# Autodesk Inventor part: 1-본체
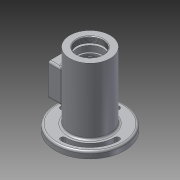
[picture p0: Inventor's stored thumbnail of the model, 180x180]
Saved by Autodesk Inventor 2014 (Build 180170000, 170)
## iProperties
Created: 2017-05
Part Number: 1-본체
Material: Aluminum 6061
Document SubType Name: Modeling
Designer: Administrator
Density: 2.71 g/cm^3
Appearance: Aluminum - Flat
Mass: 682.296 g
Surface Area: 617.383 cm^2
Volume: 251.77 cm^3
Author: Administrator
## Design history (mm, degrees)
sketch "Sketch3"
  geometry: C1 r 31 at (0, 0); 1 further point
  constraints: 1 centre point, 1 coincident
  dimensions: "d0" = 62 diameter of C1
extrude "Extrusion1" new body sketch "Sketch3" distance "d1" = 115; taper "d2" = 0 deg
workplane "Work Plane1"
sketch "Sketch4"
  geometry: L1 (0, 34)-(44, 34); L2 (44, 34)-(44, 84); L3 (44, 84)-(0, 84); L4 (0, 84)-(0, 34); L5 (31, 115)-(-31, 115) reference; 2 further points
  constraints: 8 end point, 2 parallel, 1 horizontal, 1 midpoint, 1 perpendicular, 1 vertical alignment
  dimensions: "d4" = 50 distance of L1.end L2.end; "d5" = 44 distance of L2.end L3.end; "d6" = 56 distance from line of L5 point (0, 59)
extrude "Extrusion2" join sketch "Sketch4" stored distance "d7" = 40; taper "d8" = 0 deg
sketch "Sketch5"
  geometry: L1 (-44, -34)-(-44, -84) reference; L2 (-31, -115)-(31, -115) reference; 2 further points
  constraints: 1 other
  dimensions: "d9" = 56 distance from line of L2 point (-36, -59); "d10" = 8 distance from line of L1 point (-36, -59)
emboss "Emboss1" sketch "Sketch5" dims "d11" = 0.5, "d12" = 0
workplane "Work Plane2"
sketch "Sketch7"
  geometry: C1 r 53 at (0, 0); 1 further point
  constraints: 1 centre point, 1 coincident
  dimensions: "d14" = 106 diameter of C1
extrude "Extrusion3" join sketch "Sketch7" distance "d15" = 10; taper "d16" = 0 deg
sketch "Sketch8"
  geometry: L1 (0, -20.305)-(0, 135.116); L2 (22, 0)-(16, 14); L3 (16, 14)-(12.5, 14); L4 (12.5, 14)-(12.5, 21.3); L5 (12.5, 21.3)-(10, 21.3); L6 (10, 21.3)-(10, 24); L7 (10, 24)-(16.5, 24); L8 (16.5, 24)-(16.5, 29); L9 (16.5, 29)-(17.5, 29); L10 (17.5, 29)-(17.5, 40); L11 (17.5, 40)-(26, 40); L12 (22, 0)-(0, 0); L13 (26, 40)-(26, 78); L14 (26, 78)-(17.5, 78); L15 (17.5, 78)-(17.5, 89); L16 (17.5, 89)-(18.5, 89); L17 (18.5, 89)-(18.5, 90.75); L18 (18.5, 90.75)-(17.5, 90.75); L19 (17.5, 90.75)-(17.5, 94); L20 (17.5, 94)-(20, 94); L21 (20, 94)-(20, 103); L22 (20, 103)-(24, 103); L23 (24, 103)-(24, 106); L24 (24, 106)-(0, 106); L25 (31, 115)-(-31, 115) reference
  constraints: 48 end point, 13 perpendicular, 9 parallel, 2 point on line, 1 vertical
  dimensions: "d17" = 44 diameter of L2.start L1; "d18" = 32 diameter of L2.end L1; "d19" = 14 vertical distance of L2.start L2.end; "d20" = 7.3 distance of L3.end L4.end; "d21" = 2.7 distance of L5.end L6.end; "d22" = 25 diameter of L4 L1; "d23" = 20 diameter of L6 L1; "d24" = 35 diameter of L10 L1; "d25" = 11 distance of L9.end L10.end; "d26" = 5 distance of L7.end L8.end; "d27" = 38 distance of L11.end L13.end; "d28" = 35 diameter of L15 L1; "d29" = 1.75 distance of L16.end L17.end; "d30" = 37 diameter of L17 L1; "d31" = 11 distance of L14.end L15.end; "d32" = 33 diameter of L8 L1; "d33" = 52 diameter of L13 L1; "d34" = 35 diameter of L19 L1; "d35" = 48 diameter of L23 L1; "d36" = 40 diameter of L21 L1; "d37" = 3 distance of L22.end L23.end; "d91" = 12 distance from line of L25 L22.end; "d93" = 21 distance from line of L25 L20.end
revolve "Revolution1" sketch "Sketch8" stored, may be unused: angle "d40" = 90 deg
sketch "Sketch9"
  geometry: C1 r 31 at (0, 0) reference; 1 further point
  constraints: 1 coincident
hole "Hole1" sketch "Sketch9" at (0, 0) diameter "d41" = 40.376; stored, may be unused: countersink angle "d45" = 90 deg, drill point angle "d47" = 0 deg; dims "d42" = 9, "d43" = 4, "d44" = 2, "d46" = 9
sketch "Sketch10"
  geometry: L1 (0, 0)-(0, 40) reference; L2 (-50, 0)-(-50, 40) reference; L3 (0, 0)-(-50, 0) reference; L4 (-25, 69.012)-(-25, -33.786); L5 (-50, 20)-(0, 20); L6 (31, -11)-(31, 51) reference; L7 (-4.5, 4.5)-(-45.5, 4.5); L8 (-45.5, 4.5)-(-45.5, 35.5); L9 (-45.5, 35.5)-(-4.5, 35.5); L10 (-4.5, 35.5)-(-4.5, 4.5); L11 (-4.5, 4.5)-(-45.5, 35.5); L12 (-45.5, 4.5)-(-4.5, 35.5); 6 further points
  constraints: 16 end point, 5 midpoint, 4 coincident, 2 parallel, 2 perpendicular, 1 horizontal
  dimensions: "d48" = 56 distance between parallel lines of L6 L4; "d49" = 41 distance of L8.end L9.end; "d50" = 31 distance of L7.end L8.end
hole "Hole2" sketch "Sketch10" at (-45.5, 35.5), (-45.5, 4.5), (-4.5, 4.5), (-4.5, 35.5) diameter "d51" = 2.459; stored, may be unused: countersink angle "d55" = 90 deg, drill point angle "d57" = 118 deg; dims "d52" = 6, "d53" = 4, "d54" = 2, "d56" = 8
sketch "Sketch11"
  geometry: L1 (-50, 40)-(0, 0); L2 (-41, 9)-(-9, 9); L3 (-9, 9)-(-9, 31); L4 (-9, 31)-(-41, 31); L5 (-41, 31)-(-41, 9); L6 (-41, 9)-(-9, 31); L7 (-9, 9)-(-41, 31); 2 further points
  constraints: 14 end point, 3 midpoint, 2 parallel, 1 horizontal, 1 perpendicular
  dimensions: "d58" = 22 distance of L2.end L3.end; "d59" = 32 distance of L3.end L4.end
extrude "Extrusion4" cut sketch "Sketch11" stored distance "d60" = 13; taper "d61" = 0 deg
fillet "Fillet1" dims "d65" = 3
fillet "Fillet2" dims "d66" = 3
fillet "Fillet3" dims "d67" = 0.3
fillet "Fillet4" dims "d68" = 0.3
chamfer "Chamfer2" distance "d69" = 0.7; stored, may be unused: second distance "d70" = 2, angle "d71" = 30 deg
fillet "Fillet5" dims "d72" = 3
sketch "Sketch12"
  geometry: C1 r 31 at (0, 0) reference; A1 r 41.5 centre (0, 0) between (41.5, 0) and (0, 41.5); A2 r 41.5 centre (0, 0) between (41.5, 0) and (0, 41.5); A3 r 45.5 centre (0, 0) between (45.5, 0) and (0, 45.5); A4 r 37.5 centre (0, 0) between (37.5, 0) and (0, 37.5); A5 r 4 centre (41.5, 0) between (37.5, 0) and (45.5, 0); A6 r 4 centre (0, 41.5) between (0, 45.5) and (0, 37.5); A7 r 41.5 centre (0, 0) between (-41.5, 0) and (0, -41.5); A8 r 45.5 centre (0, 0) between (-45.5, 0) and (0, -45.5); A9 r 37.5 centre (0, 0) between (-37.5, 0) and (0, -37.5); A10 r 4 centre (-41.5, 0) between (-37.5, 0) and (-45.5, 0); A11 r 4 centre (0, -41.5) between (0, -45.5) and (0, -37.5)
  constraints: 24 point on circle, 11 centre point, 10 tangent, 1 coincident
  dimensions: "d73" = 83 diameter of A1; "d74" = 4 radius of A5; "d78" = 4 radius of A10
extrude "Extrusion5" cut sketch "Sketch12" stored distance "d79" = 13; taper "d80" = 0 deg
fillet "Fillet6" dims "d81" = 3
fillet "Fillet7" dims "d82" = 3
fillet "Fillet8" dims "d83" = 3
chamfer "Chamfer3" distance "d84" = 1; stored, may be unused: second distance "d85" = 2, angle "d86" = 30 deg
fillet "Fillet9" dims "d87" = 3
chamfer "Chamfer4" distance "d88" = 1; stored, may be unused: second distance "d89" = 2, angle "d90" = 30 deg
body "Solid1"
other parameters: "d3" = 0, "d13" = -3
